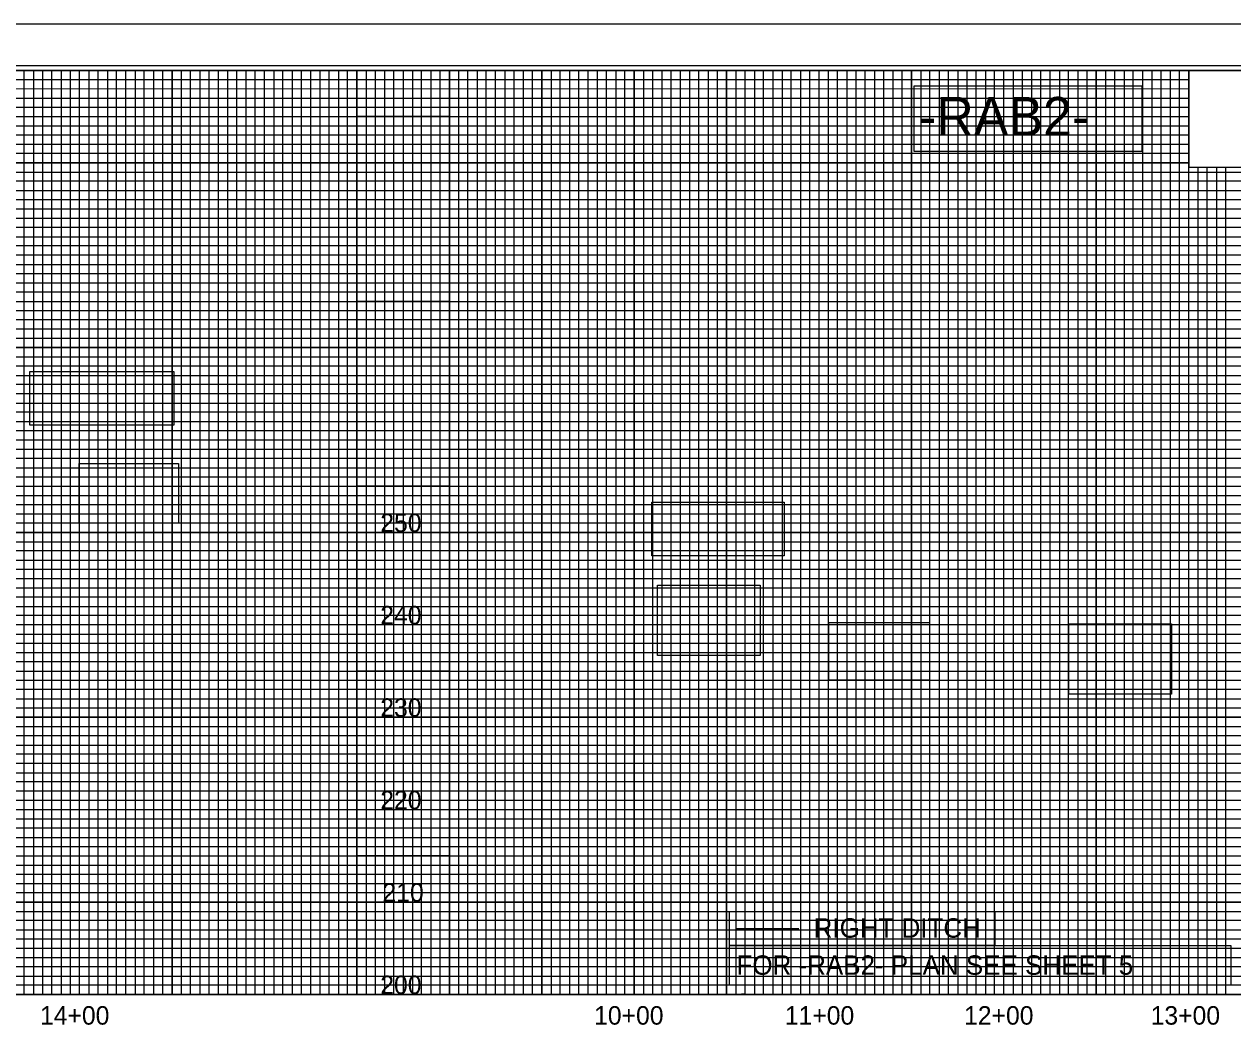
# Model space of a CAD drawing. Extents: x 1810963 to 1812934, y 722070 to 723170.
# Drawn here: x 1811600 to 1812254, y 722624 to 723170 of the extents above; entities that cross this region are included whole.
import ezdxf

# ---------------------------------------------------------------- set-up
doc = ezdxf.new("R2010")
doc.units = 0
for name, color, linetype in [('Exist Horizontal Alignment Tick Label', 7, 'Continuous'), ('Old_Level_11', 7, 'Continuous'), ('Old_Level_2', 7, 'Continuous'), ('Prop Conc 2ft 6in Curb and Gutter', 7, 'Continuous'), ('Prop RDY Traffic Signal CELL', 7, 'Continuous'), ('Prop Shade Heavy', 7, 'Continuous'), ('Prop Shade Light', 7, 'Continuous'), ('Prop Vertical Profile Ditch Grade Right', 7, 'Continuous'), ('Scratch_Level_3', 7, 'Continuous'), ('Scratch_Level_5', 7, 'Continuous'), ('Sheet Block Title CELL', 7, 'Continuous'), ('Sheet North Arrow CELL', 7, 'Continuous'), ('Sheet Symbology CELL', 7, 'Continuous'), ('Sheet Title CELL', 7, 'Continuous')]:
    doc.layers.add(name, color=color, linetype=linetype)

msp = doc.modelspace()

# ---------------------------------------------------------------- linework, layer by layer
at = {"layer": 'Old_Level_11'}
msp.add_lwpolyline([(1810976.46, 722092.33), (1812642.96, 722092.33), (1812642.96, 723147.43), (1810976.46, 723147.43)], close=True, dxfattribs=at)
at = {"layer": 'Old_Level_2'}
for p, q in [((1811830.46, 723119.88), (1811780.46, 723119.88)), ((1811830.46, 723094.88), (1811780.46, 723094.88)), ((1811830.46, 723069.88), (1811780.46, 723069.88)), ((1811830.46, 723044.88), (1811780.46, 723044.88)), ((1811830.46, 723019.88), (1811780.46, 723019.88)), ((1811830.46, 722994.88), (1811780.46, 722994.88)), ((1811830.46, 722969.88), (1811780.46, 722969.88)), ((1811830.46, 722944.88), (1811780.46, 722944.88)), ((1811830.46, 722919.88), (1811780.46, 722919.88)), ((1811830.46, 722894.88), (1811780.46, 722894.88)), ((1811830.46, 722869.88), (1811780.46, 722869.88)), ((1811830.46, 722844.88), (1811780.46, 722844.88)), ((1811830.46, 722819.88), (1811780.46, 722819.88)), ((1811830.46, 722794.88), (1811780.46, 722794.88)), ((1811830.46, 722769.88), (1811780.46, 722769.88)), ((1811830.46, 722744.88), (1811780.46, 722744.88)), ((1811830.46, 722719.88), (1811780.46, 722719.88)), ((1811830.46, 722694.88), (1811780.46, 722694.88)), ((1811830.46, 722669.88), (1811780.46, 722669.88))]:
    msp.add_line(p, q, dxfattribs=at)
for points in [[(1811780.46, 723144.88), (1811830.46, 723144.88), (1811830.46, 722644.88), (1811780.46, 722644.88)], [(1812081.83, 723136.45), (1812205.08, 723136.45), (1812205.08, 723101.06), (1812081.83, 723101.06)], [(1811603.44, 722981.99), (1811681.42, 722981.99), (1811681.42, 722952.87), (1811603.44, 722952.87)], [(1811630.24, 722932.12), (1811684, 722932.12), (1811684, 722899.94), (1811630.24, 722899.94)], [(1811940.02, 722911.36), (1812011.64, 722911.36), (1812011.64, 722882.24), (1811940.02, 722882.24)], [(1811943.03, 722866.37), (1811998.59, 722866.37), (1811998.59, 722828.25), (1811943.03, 722828.25)], [(1812035.73, 722846.14), (1812090.28, 722846.14), (1812090.28, 722814.96), (1812035.73, 722814.96)], [(1812165.5, 722845.51), (1812221.07, 722845.51), (1812221.07, 722807.39), (1812165.5, 722807.39)], [(1811981.94, 722689.88), (1812125.6, 722689.88), (1812125.6, 722671.4), (1811981.94, 722671.4)], [(1811981.94, 722671.4), (1812253.14, 722671.4), (1812253.14, 722649.87), (1811981.94, 722649.87)]]:
    msp.add_lwpolyline(points, close=True, dxfattribs=at)
at = {"layer": 'Prop Conc 2ft 6in Curb and Gutter'}
for p, q in [((1811630.46, 722644.88), (1811630.46, 723144.88)), ((1811680.46, 722644.88), (1811680.46, 723144.88)), ((1811730.46, 722644.88), (1811730.46, 723144.88)), ((1811780.46, 722644.88), (1811780.46, 723144.88)), ((1811780.46, 722644.88), (1811780.46, 723144.88)), ((1811780.46, 723144.88), (1811780.46, 722644.88)), ((1811830.46, 722644.88), (1811830.46, 723144.88)), ((1811830.46, 722644.88), (1811830.46, 723144.88)), ((1811830.46, 723144.88), (1811830.46, 722644.88)), ((1811880.46, 722644.88), (1811880.46, 723144.88)), ((1811880.46, 723144.88), (1811880.46, 722644.88)), ((1811880.46, 723144.88), (1811880.46, 722644.88)), ((1811930.46, 722644.88), (1811930.46, 723144.88)), ((1811930.46, 723144.88), (1811930.46, 722644.88)), ((1811930.46, 723144.88), (1811930.46, 722644.88)), ((1811980.46, 722644.88), (1811980.46, 723144.88)), ((1812030.46, 722644.88), (1812030.46, 723144.88)), ((1812080.46, 722644.88), (1812080.46, 723144.88)), ((1812130.46, 722644.88), (1812130.46, 723144.88)), ((1812180.46, 722644.88), (1812180.46, 723144.88)), ((1812230.46, 722644.88), (1812230.46, 723144.88)), ((1812230.42, 723094.88), (1811130.46, 723094.88)), ((1812430.41, 723044.88), (1811130.46, 723044.88)), ((1812430.46, 722994.88), (1811130.46, 722994.88)), ((1812630.46, 722944.88), (1811130.46, 722944.88)), ((1812630.46, 722894.88), (1811130.46, 722894.88)), ((1812630.46, 722844.88), (1811130.46, 722844.88)), ((1812630.46, 722794.88), (1811130.46, 722794.88)), ((1812630.46, 722744.88), (1811130.46, 722744.88)), ((1812630.46, 722694.88), (1811130.46, 722694.88))]:
    msp.add_line(p, q, dxfattribs=at)
at = {"layer": 'Prop RDY Traffic Signal CELL'}
msp.add_line((1812647.46, 723169.88), (1810963.46, 723169.88), dxfattribs=at)
at = {"layer": 'Prop Shade Heavy'}
for p, q in [((1811780.46, 723144.88), (1811830.46, 723144.88)), ((1811880.46, 723144.88), (1811930.46, 723144.88))]:
    msp.add_line(p, q, dxfattribs=at)
for points in [[(1811580.46, 722644.88), (1811630.46, 722644.88), (1811630.46, 723144.88), (1811680.46, 723144.88), (1811680.46, 722644.88), (1811730.46, 722644.88), (1811730.46, 723144.88), (1811780.46, 723144.88), (1811780.46, 722644.88), (1811830.46, 722644.88), (1811830.46, 723144.88), (1811880.46, 723144.88), (1811880.46, 722644.88), (1811930.46, 722644.88), (1811930.46, 723144.88), (1811980.46, 723144.88), (1811980.46, 722644.88), (1812030.46, 722644.88), (1812030.46, 723144.88), (1812080.46, 723144.88), (1812080.46, 722644.88), (1812130.46, 722644.88), (1812130.46, 723144.88), (1812180.46, 723144.88), (1812180.46, 722644.88), (1812230.46, 722644.88), (1812230.46, 723144.88), (1812280.46, 723144.88)], [(1811130.46, 723094.88), (1812230.42, 723094.88)], [(1812430.46, 723044.88), (1811130.46, 723044.88), (1811130.46, 722994.88), (1812430.46, 722994.88)], [(1812630.46, 722944.88), (1811130.46, 722944.88), (1811130.46, 722894.88), (1812630.46, 722894.88)], [(1812630.46, 722844.88), (1811130.46, 722844.88), (1811130.46, 722794.88), (1812630.46, 722794.88)], [(1812630.46, 722744.88), (1811130.46, 722744.88), (1811130.46, 722744.88), (1811130.46, 722694.88), (1812630.46, 722694.88)]]:
    msp.add_lwpolyline(points, dxfattribs=at)
at = {"layer": 'Prop Shade Light'}
for p, q in [((1811555.46, 723144.88), (1811605.46, 723144.88)), ((1811605.46, 723144.88), (1811605.46, 722644.88)), ((1811655.46, 722644.88), (1811655.46, 723144.88)), ((1811655.46, 723144.88), (1811705.46, 723144.88)), ((1811705.46, 723144.88), (1811705.46, 722644.88)), ((1811755.46, 722644.88), (1811755.46, 723144.88)), ((1811755.46, 723144.88), (1811805.46, 723144.88)), ((1811805.46, 723144.88), (1811805.46, 722644.88)), ((1811855.46, 722644.88), (1811855.46, 723144.88)), ((1811855.46, 723144.88), (1811905.46, 723144.88)), ((1811905.46, 723144.88), (1811905.46, 722644.88)), ((1811955.46, 722644.88), (1811955.46, 723144.88)), ((1811955.46, 723144.88), (1812005.46, 723144.88)), ((1812005.46, 723144.88), (1812005.46, 722644.88)), ((1812055.46, 722644.88), (1812055.46, 723144.88)), ((1812055.46, 723144.88), (1812105.46, 723144.88)), ((1812105.46, 723144.88), (1812105.46, 722644.88)), ((1812155.46, 722644.88), (1812155.46, 723144.88)), ((1812155.46, 723144.88), (1812205.46, 723144.88)), ((1812205.46, 723144.88), (1812205.46, 722644.88)), ((1811130.46, 723119.88), (1812230.42, 723119.88)), ((1811605.46, 722644.88), (1811655.46, 722644.88)), ((1811705.46, 722644.88), (1811755.46, 722644.88)), ((1811755.46, 722644.88), (1811755.46, 722644.88)), ((1811805.46, 722644.88), (1811855.46, 722644.88)), ((1811905.46, 722644.88), (1811955.46, 722644.88)), ((1812005.46, 722644.88), (1812055.46, 722644.88)), ((1812105.46, 722644.88), (1812155.46, 722644.88)), ((1812205.46, 722644.88), (1812255.46, 722644.88))]:
    msp.add_line(p, q, dxfattribs=at)
for points in [[(1812430.46, 723069.88), (1811130.46, 723069.88), (1811130.46, 723019.88), (1812430.46, 723019.88)], [(1812630.46, 722969.88), (1811130.46, 722969.88), (1811130.46, 722919.88), (1812455.46, 722919.88)], [(1812630.46, 722869.88), (1811130.46, 722869.88), (1811130.46, 722819.88), (1812630.46, 722819.88)], [(1812630.46, 722769.88), (1811130.46, 722769.88), (1811130.46, 722719.88), (1812630.46, 722719.88)], [(1812630.46, 722669.88), (1811130.46, 722669.88)]]:
    msp.add_lwpolyline(points, dxfattribs=at)
at = {"layer": 'Prop Vertical Profile Ditch Grade Right'}
msp.add_line((1811985.85, 722680.58), (1812019.49, 722680.58), dxfattribs=at)
at = {"layer": 'Scratch_Level_3'}
msp.add_lwpolyline([(1811180.46, 723144.88), (1812230.46, 723144.88), (1812230.46, 723092.45), (1812430.5, 723092.45), (1812430.41, 722983.83), (1812580.46, 722983.83), (1812580.46, 722644.88), (1811180.46, 722644.88)], close=True, dxfattribs=at)
at = {"layer": 'Scratch_Level_5'}
msp.add_lwpolyline([(1811180.46, 722983.83), (1811180.46, 722644.88), (1812580.46, 722644.88), (1812580.46, 722983.83)], dxfattribs=at)
at = {"layer": 'Sheet North Arrow CELL'}
msp.add_lwpolyline([(1810963.46, 722069.88), (1812647.46, 722069.88), (1812647.46, 723169.88), (1810963.46, 723169.88)], close=True, dxfattribs=at)
at = {"layer": 'Sheet Symbology CELL'}
msp.add_line((1811130.46, 722644.88), (1812630.46, 722644.88), dxfattribs=at)
msp.add_lwpolyline([(1812630.46, 723144.88), (1811130.46, 723144.88), (1811130.46, 722094.88), (1812630.46, 722094.88)], close=True, dxfattribs=at)
at = {"layer": 'Sheet Title CELL'}
for p, q in [((1812015.46, 722644.88), (1812015.46, 723144.88)), ((1812015.46, 723144.88), (1812020.46, 723144.88)), ((1812020.46, 723144.88), (1812020.46, 722644.88)), ((1812025.46, 722644.88), (1812025.46, 723144.88)), ((1812025.46, 723144.88), (1812035.46, 723144.88)), ((1812035.46, 723144.88), (1812035.46, 722644.88)), ((1812040.46, 722644.88), (1812040.46, 723144.88)), ((1812040.46, 723144.88), (1812045.46, 723144.88)), ((1812045.46, 723144.88), (1812045.46, 722644.88)), ((1812050.46, 722644.88), (1812050.46, 723144.88)), ((1812050.46, 723144.88), (1812060.46, 723144.88)), ((1812060.46, 723144.88), (1812060.46, 722644.88)), ((1812065.46, 722644.88), (1812065.46, 723144.88)), ((1812065.46, 723144.88), (1812070.46, 723144.88)), ((1812070.46, 723144.88), (1812070.46, 722644.88)), ((1812075.46, 722644.88), (1812075.46, 723144.88)), ((1812075.46, 723144.88), (1812085.46, 723144.88)), ((1812085.46, 723144.88), (1812085.46, 722644.88)), ((1812090.46, 722644.88), (1812090.46, 723144.88)), ((1812090.46, 723144.88), (1812095.46, 723144.88)), ((1812095.46, 723144.88), (1812095.46, 722644.88)), ((1812100.46, 722644.88), (1812100.46, 723144.88)), ((1812100.46, 723144.88), (1812110.46, 723144.88)), ((1812110.46, 723144.88), (1812110.46, 722644.88)), ((1812115.46, 722644.88), (1812115.46, 723144.88)), ((1812115.46, 723144.88), (1812120.46, 723144.88)), ((1812120.46, 723144.88), (1812120.46, 722644.88)), ((1812125.46, 722644.88), (1812125.46, 723144.88)), ((1812125.46, 723144.88), (1812135.46, 723144.88)), ((1812135.46, 723144.88), (1812135.46, 722644.88)), ((1812140.46, 722644.88), (1812140.46, 723144.88)), ((1812140.46, 723144.88), (1812145.46, 723144.88)), ((1812145.46, 723144.88), (1812145.46, 722644.88)), ((1812150.46, 722644.88), (1812150.46, 723144.88)), ((1812150.46, 723144.88), (1812160.46, 723144.88)), ((1812160.46, 723144.88), (1812160.46, 722644.88)), ((1812165.46, 722644.88), (1812165.46, 723144.88)), ((1812165.46, 723144.88), (1812170.46, 723144.88)), ((1812170.46, 723144.88), (1812170.46, 722644.88)), ((1812175.46, 722644.88), (1812175.46, 723144.88)), ((1812175.46, 723144.88), (1812185.46, 723144.88)), ((1812185.46, 723144.88), (1812185.46, 722644.88)), ((1812190.46, 722644.88), (1812190.46, 723144.88)), ((1812190.46, 723144.88), (1812195.46, 723144.88)), ((1812195.46, 723144.88), (1812195.46, 722644.88)), ((1812200.46, 722644.88), (1812200.46, 723144.88)), ((1812200.46, 723144.88), (1812210.46, 723144.88)), ((1812210.46, 723144.88), (1812210.46, 722644.88)), ((1812215.46, 722644.88), (1812215.46, 723144.88)), ((1812215.46, 723144.88), (1812220.46, 723144.88)), ((1812220.46, 723144.88), (1812220.46, 722644.88)), ((1812225.46, 722644.88), (1812225.46, 723144.88)), ((1812225.46, 723144.88), (1812235.46, 723144.88)), ((1812240.46, 723144.88), (1812245.46, 723144.88)), ((1812250.46, 723144.88), (1812260.46, 723144.88)), ((1811180.46, 723139.88), (1812230.42, 723139.88)), ((1812230.42, 723134.82), (1811180.46, 723134.53)), ((1811180.46, 723129.88), (1812230.42, 723129.88)), ((1812230.42, 723099.88), (1811180.46, 723099.88)), ((1812235.46, 723092.45), (1812235.46, 722644.88)), ((1812240.46, 722644.88), (1812240.46, 723092.45)), ((1812245.46, 723092.45), (1812245.46, 722644.88)), ((1812250.46, 722644.88), (1812250.46, 723092.45)), ((1811180.46, 723089.88), (1812430.46, 723089.88)), ((1812430.41, 723009.88), (1811180.46, 723009.88)), ((1812430.46, 723004.88), (1811180.46, 723004.88)), ((1812430.46, 722999.88), (1811180.46, 722999.88)), ((1811180.46, 722989.88), (1812430.46, 722989.88)), ((1812430.46, 722984.88), (1811180.46, 722984.88)), ((1811180.46, 722979.88), (1812580.46, 722979.88)), ((1812580.46, 722959.88), (1811180.46, 722959.88)), ((1811180.46, 722954.88), (1812580.46, 722954.88)), ((1812580.46, 722934.88), (1811180.46, 722934.88)), ((1811180.46, 722929.88), (1812580.46, 722929.88)), ((1812580.46, 722909.88), (1811180.46, 722909.88)), ((1811180.46, 722904.88), (1812580.46, 722904.88)), ((1812580.46, 722899.88), (1811180.46, 722899.88)), ((1811180.46, 722889.88), (1812580.46, 722889.88)), ((1812580.46, 722884.88), (1811180.46, 722884.88)), ((1811180.46, 722879.88), (1812580.46, 722879.88)), ((1812580.46, 722874.88), (1811180.46, 722874.88)), ((1811180.46, 722864.88), (1812580.46, 722864.88)), ((1812580.46, 722859.88), (1811180.46, 722859.88)), ((1811180.46, 722854.88), (1812580.46, 722854.88)), ((1812580.46, 722849.88), (1811180.46, 722849.88)), ((1811180.46, 722839.88), (1812580.46, 722839.88)), ((1812580.46, 722834.88), (1811180.46, 722834.88)), ((1811180.46, 722829.88), (1812580.46, 722829.88)), ((1812580.46, 722824.88), (1811180.46, 722824.88)), ((1811180.46, 722814.88), (1812580.46, 722814.88)), ((1812580.46, 722809.88), (1811180.46, 722809.88)), ((1811180.46, 722804.88), (1812580.46, 722804.88)), ((1812580.46, 722799.88), (1811180.46, 722799.88)), ((1811180.46, 722789.88), (1812580.46, 722789.88)), ((1812580.46, 722784.88), (1811180.46, 722784.88)), ((1811180.46, 722779.88), (1812580.46, 722779.88)), ((1812580.46, 722774.88), (1811180.46, 722774.88)), ((1811180.46, 722764.88), (1812580.46, 722764.88)), ((1812580.46, 722759.88), (1811180.46, 722759.88)), ((1812580.46, 722754.88), (1811180.46, 722754.88)), ((1812580.46, 722749.88), (1811180.46, 722749.88)), ((1811180.46, 722739.88), (1812580.46, 722739.88)), ((1812580.46, 722734.88), (1811180.46, 722734.88)), ((1811180.46, 722729.88), (1812580.46, 722729.88)), ((1812580.46, 722724.88), (1811180.46, 722724.88)), ((1811180.46, 722714.88), (1812580.46, 722714.88)), ((1812580.46, 722709.88), (1811180.46, 722709.88)), ((1811180.46, 722704.88), (1812580.46, 722704.88)), ((1812580.46, 722699.88), (1811180.46, 722699.88)), ((1811180.46, 722689.88), (1812580.46, 722689.88)), ((1812580.46, 722684.88), (1811180.46, 722684.88)), ((1811180.46, 722679.88), (1812580.46, 722679.88)), ((1812580.46, 722674.88), (1811180.46, 722674.88)), ((1811180.46, 722664.88), (1812580.46, 722664.88)), ((1812580.46, 722659.88), (1811180.46, 722659.88)), ((1811180.46, 722654.88), (1812580.46, 722654.88)), ((1812020.46, 722644.88), (1812025.46, 722644.88)), ((1812035.46, 722644.88), (1812040.46, 722644.88)), ((1812045.46, 722644.88), (1812050.46, 722644.88)), ((1812060.46, 722644.88), (1812065.46, 722644.88)), ((1812070.46, 722644.88), (1812075.46, 722644.88)), ((1812085.46, 722644.88), (1812090.46, 722644.88)), ((1812095.46, 722644.88), (1812100.46, 722644.88)), ((1812110.46, 722644.88), (1812115.46, 722644.88)), ((1812120.46, 722644.88), (1812125.46, 722644.88)), ((1812135.46, 722644.88), (1812140.46, 722644.88)), ((1812145.46, 722644.88), (1812150.46, 722644.88)), ((1812160.46, 722644.88), (1812165.46, 722644.88)), ((1812170.46, 722644.88), (1812175.46, 722644.88)), ((1812185.46, 722644.88), (1812190.46, 722644.88)), ((1812195.46, 722644.88), (1812200.46, 722644.88)), ((1812210.46, 722644.88), (1812215.46, 722644.88)), ((1812220.46, 722644.88), (1812225.46, 722644.88)), ((1812235.46, 722644.88), (1812240.46, 722644.88)), ((1812245.46, 722644.88), (1812250.46, 722644.88))]:
    msp.add_line(p, q, dxfattribs=at)
for points in [[(1811595.46, 722644.88), (1811600.46, 722644.88), (1811600.46, 723144.88), (1811610.46, 723144.88), (1811610.46, 722644.88), (1811615.46, 722644.88), (1811615.46, 723144.88), (1811620.46, 723144.88), (1811620.46, 722644.88), (1811625.46, 722644.88), (1811625.46, 723144.88), (1811635.46, 723144.88), (1811635.46, 722644.88), (1811640.46, 722644.88), (1811640.46, 723144.88), (1811645.46, 723144.88), (1811645.46, 722644.88), (1811650.46, 722644.88), (1811650.46, 723144.88), (1811660.46, 723144.88), (1811660.46, 722644.88), (1811665.46, 722644.88), (1811665.46, 723144.88), (1811670.46, 723144.88), (1811670.46, 722644.88), (1811675.46, 722644.88), (1811675.46, 723144.88), (1811685.46, 723144.88), (1811685.46, 722644.88), (1811690.46, 722644.88), (1811690.46, 723144.88), (1811695.46, 723144.88), (1811695.46, 722644.88), (1811700.46, 722644.88), (1811700.46, 723144.88), (1811710.46, 723144.88)], [(1811710.46, 723144.88), (1811710.46, 722644.88), (1811715.46, 722644.88), (1811715.46, 723144.88), (1811720.46, 723144.88), (1811720.46, 722644.88), (1811725.46, 722644.88), (1811725.46, 723144.88), (1811735.46, 723144.88), (1811735.46, 722644.88), (1811740.46, 722644.88), (1811740.46, 723144.88), (1811745.46, 723144.88), (1811745.46, 722644.88), (1811750.46, 722644.88), (1811750.46, 723144.88), (1811760.46, 723144.88), (1811760.46, 722644.88), (1811765.46, 722644.88), (1811765.46, 723144.88), (1811770.46, 723144.88), (1811770.46, 722644.88), (1811775.46, 722644.88), (1811775.46, 723144.88), (1811785.46, 723144.88), (1811785.46, 722644.88), (1811790.46, 722644.88), (1811790.46, 723144.88), (1811795.46, 723144.88), (1811795.46, 722644.88), (1811800.46, 722644.88), (1811800.46, 723144.88), (1811810.46, 723144.88), (1811810.46, 722644.88), (1811815.46, 722644.88), (1811815.46, 723144.88), (1811820.46, 723144.88), (1811820.46, 722644.88), (1811825.46, 722644.88), (1811825.46, 723144.88), (1811835.46, 723144.88), (1811835.46, 722644.88), (1811835.46, 722644.88), (1811840.46, 722644.88), (1811840.46, 723144.88), (1811845.46, 723144.88), (1811845.46, 722644.88), (1811850.46, 722644.88), (1811850.46, 723144.88), (1811860.46, 723144.88), (1811860.46, 722644.88), (1811865.46, 722644.88), (1811865.46, 723144.88), (1811870.46, 723144.88), (1811870.46, 722644.88), (1811875.46, 722644.88), (1811875.46, 723144.88), (1811885.46, 723144.88), (1811885.46, 722644.88), (1811890.46, 722644.88), (1811890.46, 723144.88), (1811895.46, 723144.88), (1811895.46, 722644.88), (1811900.46, 722644.88), (1811900.46, 723144.88), (1811910.46, 723144.88), (1811910.46, 722644.88), (1811915.46, 722644.88), (1811915.46, 723144.88), (1811920.46, 723144.88), (1811920.46, 722644.88), (1811925.46, 722644.88), (1811925.46, 723144.88), (1811935.46, 723144.88), (1811935.46, 722644.88), (1811940.46, 722644.88), (1811940.46, 723144.88), (1811945.46, 723144.88), (1811945.46, 722644.88), (1811950.46, 722644.88), (1811950.46, 723144.88), (1811960.46, 723144.88), (1811960.46, 722644.88), (1811965.46, 722644.88), (1811965.46, 723144.88), (1811970.46, 723144.88), (1811970.46, 722644.88), (1811975.46, 722644.88), (1811975.46, 723144.88), (1811985.46, 723144.88), (1811985.46, 722644.88), (1811990.16, 722645.43), (1811990.46, 722644.88), (1811990.46, 723144.88), (1811995.46, 723144.88), (1811995.46, 722644.88), (1812000.46, 722644.88), (1812000.46, 723144.88), (1812010.46, 723144.88), (1812010.46, 722644.88), (1812015.46, 722644.88)], [(1812230.42, 723124.88), (1811180.46, 723124.88), (1811180.46, 723114.88), (1812230.42, 723114.88)], [(1812230.42, 723109.88), (1811180.46, 723109.88), (1811180.46, 723104.88), (1812230.42, 723104.88)], [(1812430.46, 723084.88), (1811180.46, 723084.88), (1811180.46, 723079.88), (1812430.46, 723079.88)], [(1812430.46, 723074.88), (1811180.46, 723074.88), (1811180.46, 723064.88), (1812430.46, 723064.88)], [(1812430.46, 723059.88), (1811180.46, 723059.88), (1811180.46, 723054.88), (1812430.46, 723054.88)], [(1812430.46, 723049.88), (1811180.46, 723049.88), (1811180.46, 723039.88), (1812430.46, 723039.88)], [(1812430.46, 723034.78), (1811180.56, 723034.78), (1811180.56, 723029.88), (1812430.46, 723029.88)], [(1812430.46, 723024.88), (1811180.46, 723024.88), (1811180.46, 723014.88), (1812430.46, 723014.88)], [(1812580.46, 722974.88), (1811180.46, 722974.88), (1811180.46, 722964.88), (1812580.46, 722964.88)], [(1812580.46, 722949.88), (1811180.46, 722949.88), (1811180.46, 722939.88), (1812580.46, 722939.88)], [(1812580.46, 722924.88), (1811180.46, 722924.88), (1811180.46, 722914.88), (1812580.46, 722914.88)], [(1812580.46, 722649.88), (1811180.46, 722649.88)]]:
    msp.add_lwpolyline(points, dxfattribs=at)

# ---------------------------------------------------------------- texts
at = {"layer": 'Exist Horizontal Alignment Tick Label'}
for s, height, p in [('-RAB2-', 21, (1812084.55, 723109.49)), ('RIGHT DITCH', 10.5, (1812027.54, 722675.64)), ('FOR -RAB2- PLAN SEE SHEET 5', 10.5, (1811985.84, 722655.58))]:
    msp.add_text(s, height=height, rotation=360, dxfattribs=at).set_placement(p)
at = {"layer": 'Old_Level_2'}
for s, p in [('250', (1811793.1, 722895.13)), ('240', (1811793.1, 722845.13)), ('230', (1811793.1, 722795.13)), ('220', (1811793.1, 722745.13)), ('210', (1811794.29, 722695.13)), ('200', (1811793.1, 722645.13))]:
    msp.add_text(s, height=10, dxfattribs=at).set_placement(p)
at = {"layer": 'Sheet Block Title CELL'}
for s, p in [('14+00', (1811609.01, 722628.6)), ('10+00', (1811908.78, 722628.6)), ('11+00', (1812011.94, 722628.6)), ('12+00', (1812108.92, 722628.6)), ('13+00', (1812209.84, 722628.6))]:
    msp.add_text(s, height=10, dxfattribs=at).set_placement(p)

doc.saveas('drawing.dxf')
